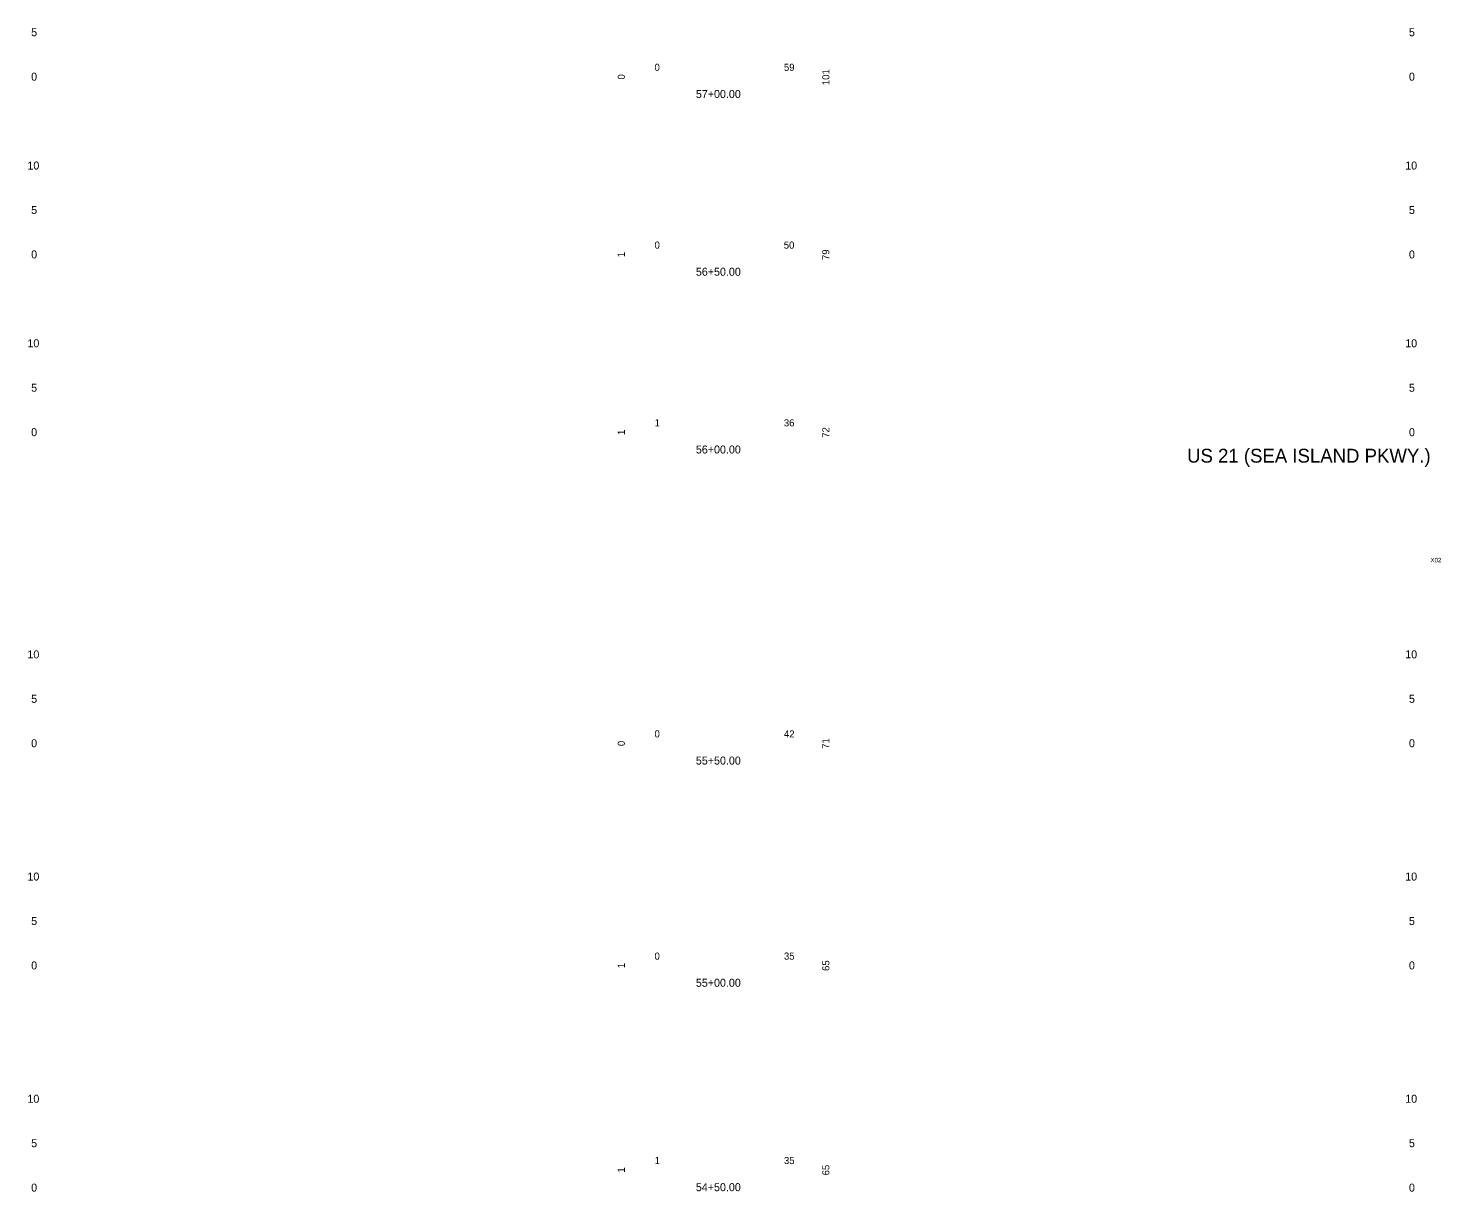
# Model space of a CAD drawing. Extents: x 971 to 1131, y 2203 to 6043.
# Drawn here: x 971.5 to 1130.4, y 2341.9 to 2472.8 of the extents above; entities that cross this region are included whole.
import ezdxf

# ---------------------------------------------------------------- set-up
doc = ezdxf.new("R2010")
doc.units = 0
for name, color, linetype in [('RD_SHT_Misc1', 7, 'Continuous'), ('RD_SHT_TX', 7, 'Continuous'), ('RD_XS_TX_Station', 7, 'Continuous')]:
    doc.layers.add(name, color=color, linetype=linetype)

msp = doc.modelspace()

# ---------------------------------------------------------------- texts
at = {"layer": 'RD_SHT_Misc1'}
for s, p in [('0', (1041.97, 2467.97)), ('59', (1056.53, 2467.97)), ('0', (1041.97, 2447.97)), ('50', (1056.51, 2447.97)), ('36', (1056.52, 2427.97)), ('0', (1041.97, 2392.97)), ('42', (1056.53, 2392.97)), ('0', (1041.97, 2367.97)), ('35', (1056.53, 2367.97)), ('35', (1056.53, 2344.97))]:
    msp.add_text(s, height=0.8, dxfattribs=at).set_placement(p)
for s, rotation, p in [('101', 90, (1061.64, 2466.37)), ('0', 90, (1038.63, 2467)), ('1', 90, (1038.63, 2447.01)), ('79', 90, (1061.64, 2446.69)), ('1', 360, (1041.98, 2427.97)), ('1', 90, (1038.63, 2427.01)), ('72', 90, (1061.64, 2426.69)), ('0', 90, (1038.63, 2392)), ('71', 90, (1061.64, 2391.69)), ('65', 90, (1061.64, 2366.7)), ('1', 90, (1038.63, 2367.01)), ('1', 360, (1041.98, 2344.97)), ('1', 90, (1038.63, 2344.01)), ('65', 90, (1061.64, 2343.7))]:
    msp.add_text(s, height=0.8, rotation=rotation, dxfattribs=at).set_placement(p)
at = {"layer": 'RD_SHT_TX'}
for s, height, p in [('5', 0.9, (971.84, 2471.87)), ('5', 0.9, (1126.84, 2471.87)), ('0', 0.9, (971.84, 2466.87)), ('0', 0.9, (1126.84, 2466.87)), ('10', 0.9, (971.42, 2456.87)), ('10', 0.9, (1126.42, 2456.87)), ('5', 0.9, (971.84, 2451.87)), ('5', 0.9, (1126.84, 2451.87)), ('0', 0.9, (971.84, 2446.87)), ('0', 0.9, (1126.84, 2446.87)), ('10', 0.9, (971.42, 2436.87)), ('10', 0.9, (1126.42, 2436.87)), ('5', 0.9, (971.84, 2431.87)), ('5', 0.9, (1126.84, 2431.87)), ('0', 0.9, (971.84, 2426.87)), ('0', 0.9, (1126.84, 2426.87)), ('US 21 (SEA ISLAND PKWY.)', 1.5625, (1101.88, 2423.89)), ('10', 0.9, (971.42, 2401.87)), ('10', 0.9, (1126.42, 2401.87)), ('5', 0.9, (971.84, 2396.87)), ('5', 0.9, (1126.84, 2396.87)), ('0', 0.9, (971.84, 2391.87)), ('0', 0.9, (1126.84, 2391.87)), ('10', 0.9, (971.42, 2376.87)), ('10', 0.9, (1126.42, 2376.87)), ('5', 0.9, (971.84, 2371.87)), ('5', 0.9, (1126.84, 2371.87)), ('0', 0.9, (971.84, 2366.87)), ('0', 0.9, (1126.84, 2366.87)), ('10', 0.9, (971.42, 2351.87)), ('10', 0.9, (1126.42, 2351.87)), ('5', 0.9, (971.84, 2346.87)), ('5', 0.9, (1126.84, 2346.87)), ('0', 0.9, (971.84, 2341.87)), ('0', 0.9, (1126.84, 2341.87))]:
    msp.add_text(s, height=height, dxfattribs=at).set_placement(p)
msp.add_text('X02', height=0.5, rotation=360, dxfattribs=at).set_placement((1129.26, 2412.68))
at = {"layer": 'RD_XS_TX_Station'}
for s, p in [('57+00.00', (1046.62, 2464.92)), ('56+50.00', (1046.62, 2444.92)), ('56+00.00', (1046.62, 2424.92)), ('55+50.00', (1046.62, 2389.92)), ('55+00.00', (1046.62, 2364.92)), ('54+50.00', (1046.62, 2341.92))]:
    msp.add_text(s, height=0.9, dxfattribs=at).set_placement(p)

doc.saveas('drawing.dxf')
